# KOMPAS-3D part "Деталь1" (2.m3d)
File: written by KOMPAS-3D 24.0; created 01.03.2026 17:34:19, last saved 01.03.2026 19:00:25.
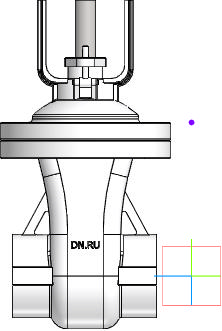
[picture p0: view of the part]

Document properties: Автор: R2D2; Полное имя файла: E:\Работа\Зайцев\GVWR3131M-2W-F-S Задвижка клиновая с выдвижным штоком DN.ru Ду50-200 Ру63\DN50\исходные материалы\2.m3d

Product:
- Body: Твердое тело1  | qty 1
    Масса: 12.23036
- Part/product: Деталь1
    Масса: 12.23036
    additional columns: Типовые

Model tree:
1. Твердое тело1  (labels: Твердое тело1)
2. Точка:1
     Y = 130.5; Координата Y = 130.5
3. Эскиз:1
4. Элемент выдавливания:1
     Расстояние 1 = 500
